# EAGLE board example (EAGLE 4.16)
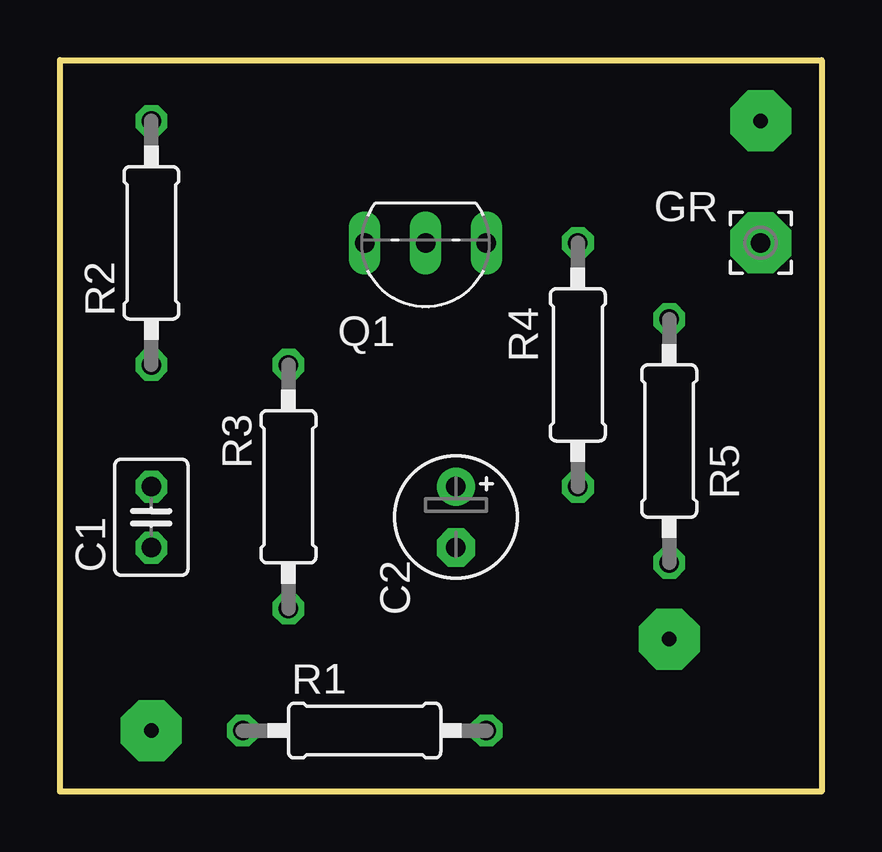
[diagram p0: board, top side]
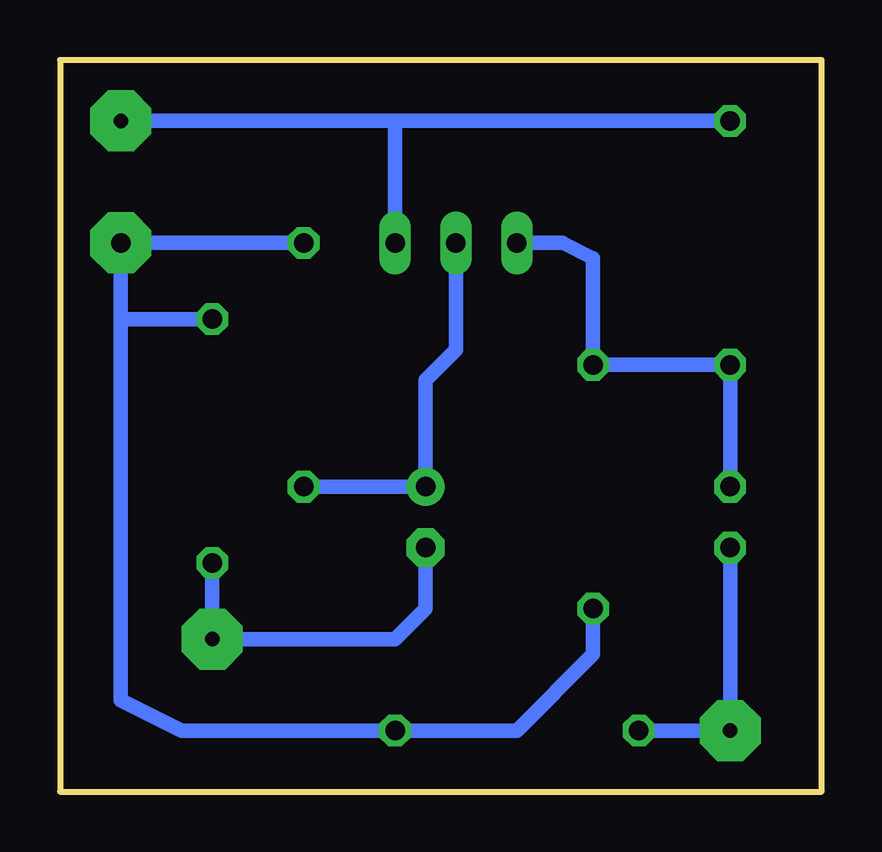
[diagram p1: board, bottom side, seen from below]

Size 31.75 x 30.48 mm. Coordinates in mm from the lower left corner, seen from the top.
Outline: 0,0 0,30.48 31.75,30.48 31.75,0 0,0
Copper layers (1*16): Top 0.035mm / dielectric 1.5mm / Bottom 0.035mm
Design rules "default": minimum track width 10mil, minimum drill 24mil, track to track 8mil, track to pad 8mil, pad to pad 8mil, via to via 8mil, smd to smd 8mil, copper to edge 40mil, drill to drill 8mil, minimum pad ring 10mil, minimum via ring 8mil, stop-mask expansion 4mil, vias tented up to drill 0mil, thermal gap 10mil

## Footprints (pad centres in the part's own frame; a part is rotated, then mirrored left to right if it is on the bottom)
C025-030X050 = drill 0.813 octagon: 1 -1.27,0; 2 1.27,0
E2,5-5 = drill 0.813 pad 1.6 round: + -1.27,0 | drill 0.813 pad 1.6 octagon: - 1.27,0
2,54/0,8 = drill 0.813 pad 2.54 octagon: 1 0,0
TO92- = drill 0.813 long: 1 2.54,0; 2 0,0; 3 -2.54,0
0207/10 = drill 0.813 octagon: 1 -5.08,0; 2 5.08,0

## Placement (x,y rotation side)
C1  [C025-030X050]  3.81,11.43 90 top
C2  [E2,5-5]  16.51,11.43 270 top
GR  [2,54/0,8]  29.21,22.86 0 top
Q1  [TO92-]  15.24,22.86 180 top
R1  [0207/10]  12.7,2.54 0 top
R2  [0207/10]  3.81,22.86 90 top
R3  [0207/10]  9.53,12.7 90 top
R4  [0207/10]  21.59,17.78 270 top
R5  [0207/10]  25.4,14.61 90 top

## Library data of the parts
C1 C2 R1-R5 = rcl
GR = wirepad
Q1 = transistor-fet

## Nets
S1: GR.1 R1.2 R3.1 R4.1 R5.2
S$1: C1.1 R1.1
S$2: C2.+ Q1.2 R4.2
S$3: Q1.3 R2.2
S$5: C1.2 Q1.1 R2.1 R3.2
S$7: C2.- R5.1

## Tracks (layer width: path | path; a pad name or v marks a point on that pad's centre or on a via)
S1
  Bottom 0.61: 29.21,19.68 R5.2 | 29.21,19.68 29.21,3.81 26.67,2.54 R1.2 12.7,2.54 9.53,5.71 R3.1 | R4.1 GR.1 29.21,19.68
S$1  (via drill 0.6 pad 2.54)
  Bottom 0.61: R1.1 v3.81,2.54 C1.1
S$2
  Bottom 0.61: Q1.2 15.24,18.41 16.51,17.14 C2.+ R4.2
S$3  (via drill 0.6 pad 2.54)
  Bottom 0.61: v29.21,27.94 17.78,27.94 | 17.78,27.94 R2.2 | Q1.3 17.78,27.94
S$5
  Bottom 0.61: Q1.1 10.79,22.86 9.53,22.23 R3.2 R2.1 C1.2
S$7  (via drill 0.6 pad 2.54)
  Bottom 0.61: R5.1 v25.4,6.35 17.78,6.35 16.51,7.62 C2.-

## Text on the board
tOrigins: AMZ-FX | +9 | BUFFER | IN | OUT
